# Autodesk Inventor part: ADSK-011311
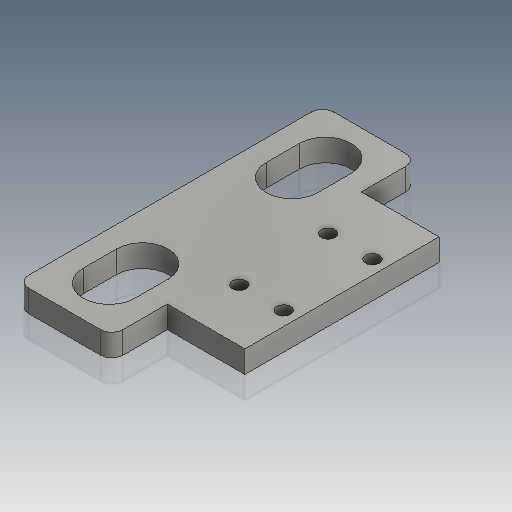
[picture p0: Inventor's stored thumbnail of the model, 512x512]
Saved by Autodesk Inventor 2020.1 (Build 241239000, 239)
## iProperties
Created: 1999-12
Part Number: ADSK-011311
Material: Aluminum
Description: PLT-24,FA,CP,02,034,019,YY1111,MANIFOLD,VACUUM
Document SubType Name: Modeling
Designer: sspink
Density: 2.71 g/cm^3
Appearance: Steel
Mass: 49.9705 g
Surface Area: 86.576 cm^2
Volume: 18.4393 cm^3
Control State: 0
Checked Out: False
Last Check In By: sspink
Last Check In Date: 1999-12-22
Master: False
Shininess: 0.0
Length Units: 11269
Angle Units: 11279
Time Units: 11290
Mass Units: 11283
Length Display Precision: 3
Angle Display Precision: 2
Compacted: True
Dimensions: 49,2x6,4x87,3 mm
Mass: 0,05 kg
DocNumber: ADSK-011311.ipt
Folder: 01 - Themengebiete\Simplification\01 - Packaging machine\
VDS_Category: 3D Komponenten
Density: 0.0
Volumn: 0.0
Area: 0.0
PropertySet Name: Model Information
Author: sspink
Revision Number: -
Title: Zylinder
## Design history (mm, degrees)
node "Extrusion1" dims "d2" = 55.5625, "d3" = 0
node "Extrusion2" dims "d6" = 6.35, "d7" = 0
node "Hole2" dims "d15" = 3.9624, "d16" = 9.525, "d17" = 6.35, "d18" = 60 deg, "d19" = 19.05, "d20" = 118 deg
node "Fillet1" dims "d21" = 3.175
node "Extrusion3" dims "d30" = 25.4, "d31" = 0
node "Solide1"
node "Corps solides"
node "Corps surfaciques"
sketch "Sketch1"
  geometry: L1 (0, 12.7)-(-49.213, 12.7); L2 (-49.213, 12.7)-(-49.213, 19.05); L3 (-49.213, 19.05)-(0, 19.05); L4 (0, 19.05)-(0, 12.7)
  constraints: 8 end point, 2 parallel, 1 horizontal, 1 perpendicular
  dimensions: "d0" = 6.35 distance of L1.end L2.end; "d1" = 49.2125 distance of L2.end L3.end
sketch "Sketch2"
  geometry: L1 (0, 0)-(0, 55.562) reference; L2 (26.987, 55.562)-(0, 55.562); L3 (0, 55.562)-(0, 71.437); L4 (0, 71.437)-(26.987, 71.437); L5 (26.987, 71.437)-(26.987, 55.562); L6 (26.987, 0)-(0, 0); L7 (0, 0)-(0, -15.875); L8 (0, -15.875)-(26.987, -15.875); L9 (26.987, -15.875)-(26.987, 0)
  constraints: 16 end point, 6 parallel, 2 horizontal, 2 perpendicular
  dimensions: "d4" = 15.875 distance of L4.end L2.start; "d5" = 15.875 distance of L8.end L6.start (= d4); "d32" = 26.9875 distance between parallel lines of L7 L9; "d33" = 26.9875 distance between parallel lines of L5 L3
sketch "Sketch4"
  geometry: L1 (0, 55.562)-(-22.225, 55.562) reference; L2 (0, 0)-(0, 55.562) reference; 4 further points
  dimensions: "d34" = 15.08125 distance from line of point (-3.967, 40.481) L1; "d35" = 3.96672 distance from line of L2 point (-3.967, 40.481); "d36" = 12.70203 distance of point (-16.669, 40.481) point (-3.967, 40.481); "d37" = 12.7 distance of point (-16.669, 15.081) point (-3.969, 15.081); "d38" = 3.96875 distance from line of L2 point (-3.969, 15.081); "d39" = 25.4 distance of point (-3.969, 15.081) point (-3.967, 40.481); "d40" = 25.4 distance of point (-16.669, 15.081) point (-16.669, 40.481); "d41" = 15.08125 distance from line of point (-16.669, 40.481) L1
sketch "Sketch5"
  geometry: L1 (-25.4, -15.875)-(-46.037, -15.875) reference; L2 (0, 55.562)-(0, 0) reference; L3 (-46.037, 71.438)-(-25.4, 71.438) reference; L4 (-49.213, -12.7)-(-49.213, 68.263) reference; L5 (-35.719, 71.438)-(-35.719, -15.875); L6 (-49.213, 27.781)-(0, 27.781); L7 (-28.293, 58.738)-(-28.293, 49.213); L8 (-43.145, 49.213)-(-43.145, 58.738); L9 (-28.293, -3.175)-(-28.293, 6.35); L10 (-43.145, 6.35)-(-43.145, -3.175); A1 r 7.426 centre (-35.719, 58.738) between (-28.293, 58.738) and (-43.145, 58.738); A2 r 7.426 centre (-35.719, 49.213) between (-43.145, 49.213) and (-28.293, 49.213); A3 r 7.426 centre (-35.719, 6.35) between (-28.293, 6.35) and (-43.145, 6.35); A4 r 7.426 centre (-35.719, -3.175) between (-43.145, -3.175) and (-28.293, -3.175)
  constraints: 12 end point, 8 point on circle, 8 tangent, 4 centre point, 4 midpoint, 4 point on line, 3 equal radius, 1 collinear, 1 parallel, 1 vertical
  dimensions: "d27" = 9.525 distance of L7.start L7.end; "d28" = 12.7 distance from line of A1.centre L3; "d29" = 12.7 distance from line of A4.centre L1 (= d28); "d42" = 7.42597 radius of A2
